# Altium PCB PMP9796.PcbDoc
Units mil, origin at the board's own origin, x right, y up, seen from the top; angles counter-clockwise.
Board outline 2600 x 2200 mil, 2 copper layers (Top Layer, Bottom Layer), stack 40 mil thick; 34 components, 11 nets, 92 pads, 50 vias.
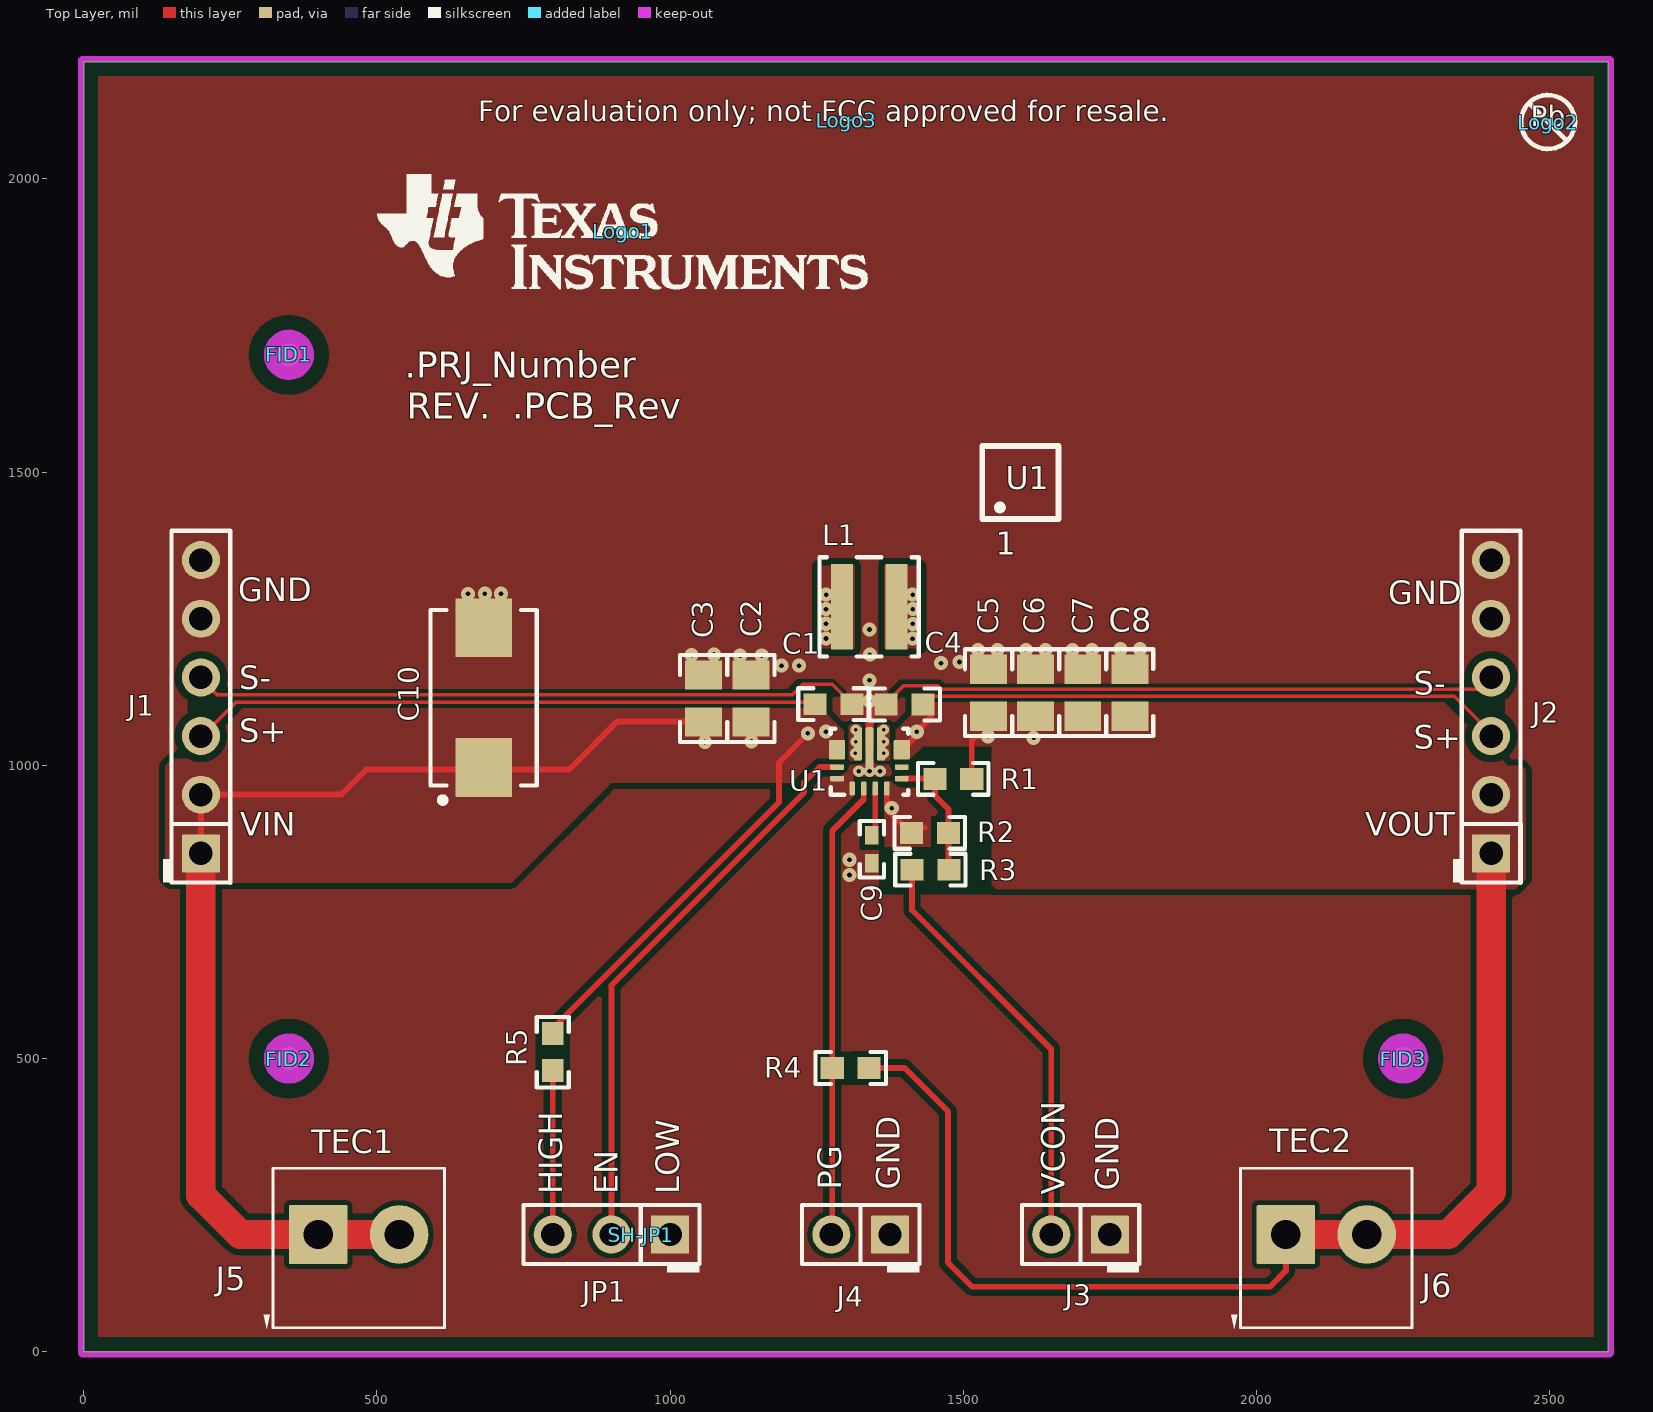
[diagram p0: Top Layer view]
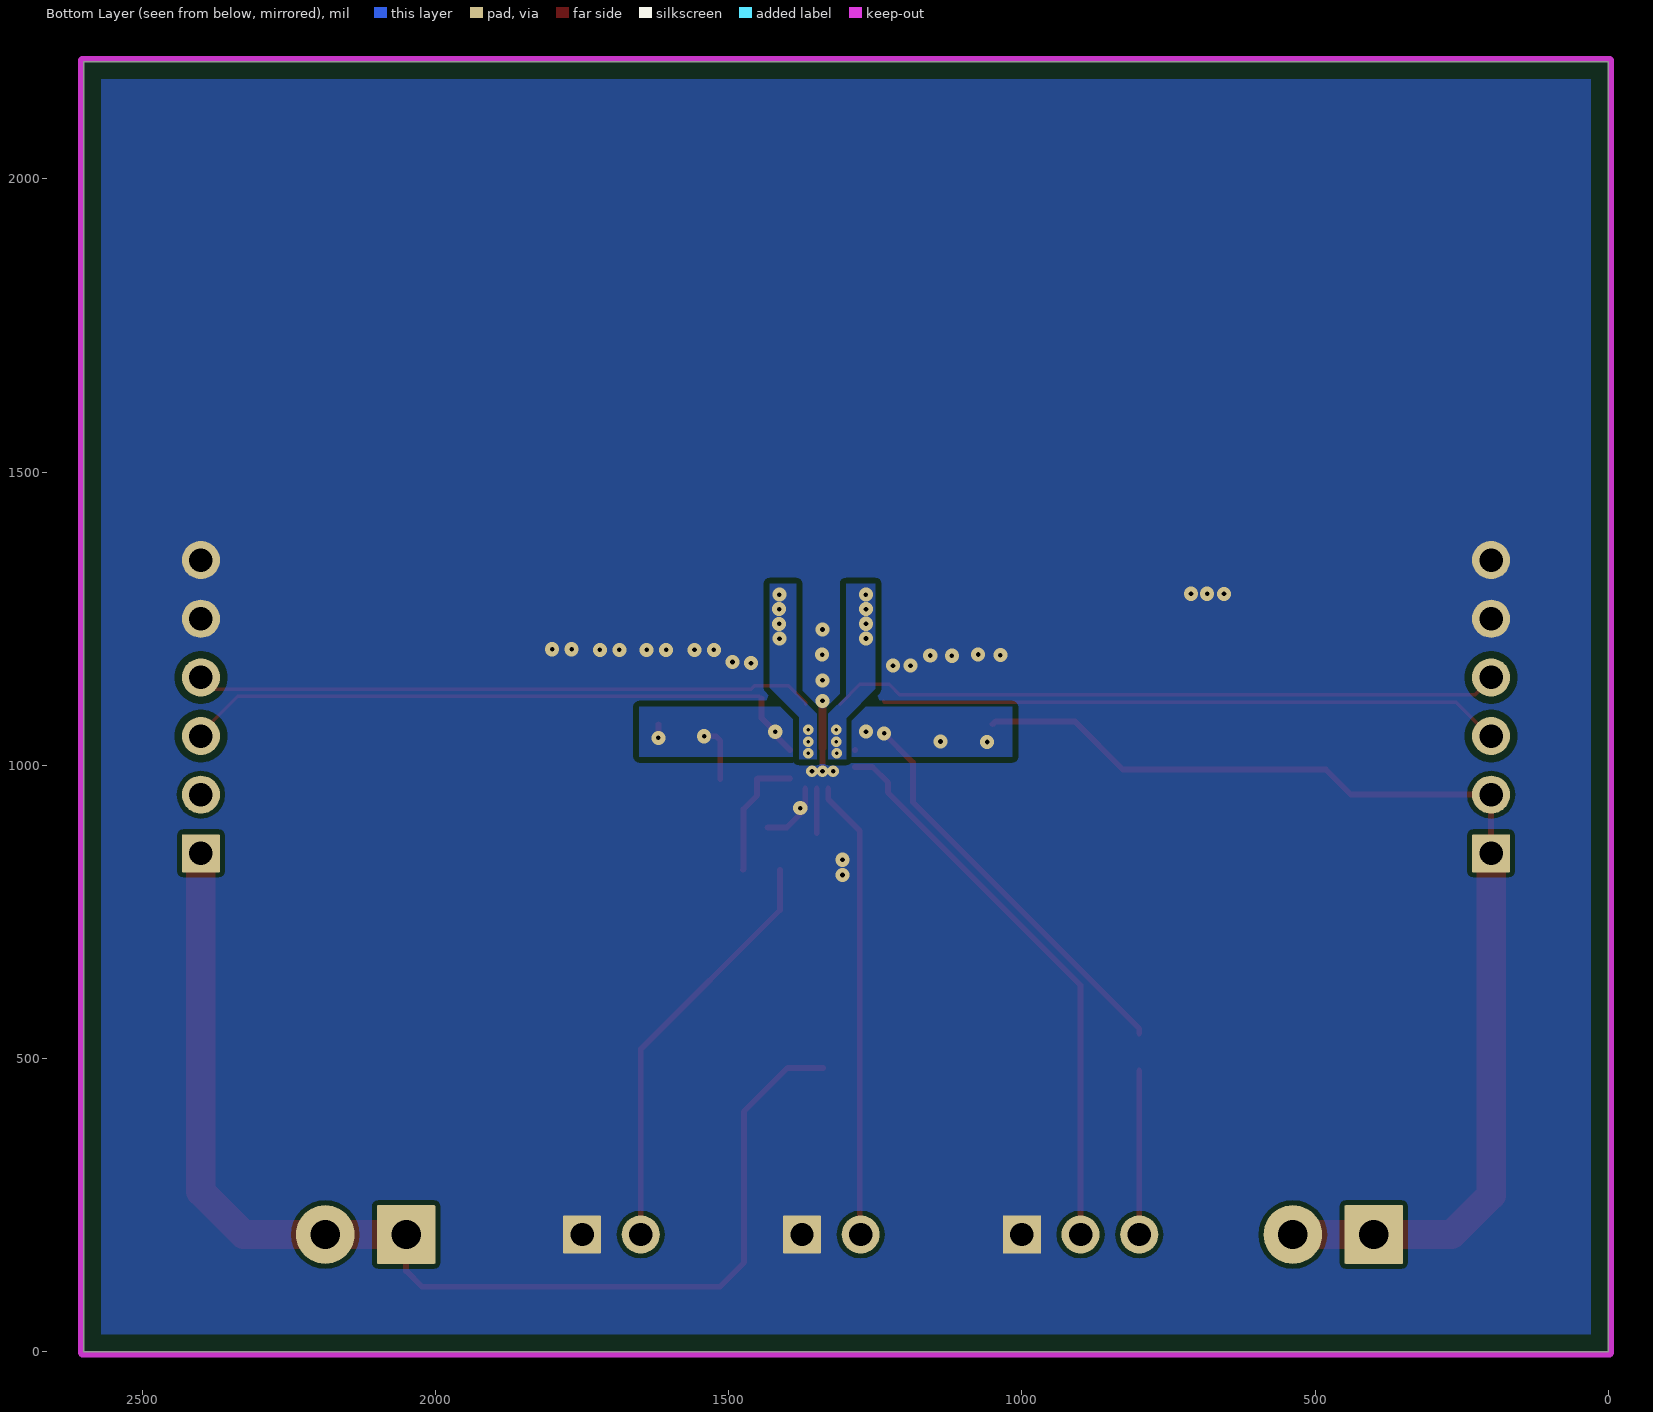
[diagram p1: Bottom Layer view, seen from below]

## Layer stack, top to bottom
Top Solder: solder mask 0.4, Solder Resist, Dk 3.5
Top Layer: signal copper 1.4
Dielectric1: core 37.2, FR-4, Dk 4.8
Bottom Layer: signal copper 1.4
Bottom Solder: solder mask 0.4, Solder Resist, Dk 3.5

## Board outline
0,0 2600,0 2600,2200 0,2200

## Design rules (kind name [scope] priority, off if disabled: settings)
AcuteAngle [All] p1: minimum=4.50000000000000E+0001 checktracksonly=FALSE
AssemblyTestPointUsage [All] p1: valid=2
Clearance Clearance_U1_Poly [InNamedPolygon('L1_L01_P015') Or InNamedPolygon('L2_L01_P016')] p1: gap=5.9
Clearance Clearance_U1 [InComponent('U1')] p2: gap=5.9
Clearance Clearance_JP4 [InComponent('JP4')] p3: gap=5.9
Clearance Clearance_Keepouts [((IsTrack Or IsArc) And Not InPoly) And IsFree and IsKeepOut vs ((IsTrack Or IsArc) And Not InPoly) And IsFree and IsKeepOut] p4: gap=0
Clearance Clearance_Pad [((ObjectKind = 'Pad') And (Layer = 'MultiLayer'))] p5: gap=8 except(6: Track-Track)
Clearance Clearance_BoardEdge_MountingHoles [OnCopper and InComponentClass('Mounting Holes') vs IsKeepOut] p6: gap=40
Clearance Clearance_BoardEdge_Poly [OnCopper and InPoly vs IsKeepOut] p7: gap=25
Clearance Clearance_BoardEdge [OnCopper and Not InComponentClass('Logo') and not InComponentClass('FiducialMark') and not InRegion(1000,500,4000,800) and Not IsKeepout vs IsKeepOut] p8: gap=36
Clearance Clearance_Poly [InPolygon] p9: gap=10
Clearance [All] p10: gap=7.87 except(6: Track-Track)
ComponentClearance ComponentClearance_1 [(InComponent('J1') OR InComponent('J2') OR InComponent('J3') OR InComponent('J4') OR InComponent('J5') OR InComponent('J6') OR InComponent('J8')OR InComponent('JP1') OR InComponent('JP2') OR InComponent('JP3') OR InComponent('JP4') OR InComponent('L1') OR InComponent('U1'))] p1: gap=0 collisioncheckmode=3 verticalgap=0 showdistances=FALSE
ComponentClearance ComponentClearance_Logo [InComponentClass('Logo')] p2: gap=50 collisioncheckmode=3 verticalgap=10 showdistances=FALSE
ComponentClearance ComponentClearance_ScrewToNut [(HasFootprint('NY PMS 440 0025 PH')) vs (HasFootprint('Keystone_1902C'))] p3: gap=5 collisioncheckmode=3 verticalgap=10 showdistances=FALSE
ComponentClearance ComponentClearance_MountingHoles [InComponentClass('Mounting Holes')] p4: gap=50 collisioncheckmode=3 verticalgap=0 showdistances=FALSE
ComponentClearance ComponentClearance_SmallPassives [HasFootprint('0201*') or HasFootprint('0402*') or HasFootprint('0508') or HasFootprint('0603*') or HasFootprint('0612') or HasFootprint('0805*') or HasFootprint('0815*') or HasFootprint('0830*') or HasFootprint('1206*') or HasFootprint('1210*') or HasFootprint('1808*') or HasFootprint('1812*') or HasFootprint('1825*') or HasFootprint('2010*') or HasFootprint('2220*') or HasFootprint('2225*') or HasFootprint('2512*') or HasFootprint('2728*') or HasFootprint('3518*') vs HasFootprint('0201*') or HasFootprint('0402*') or HasFootprint('0508') or HasFootprint('0603*') or HasFootprint('0612') or HasFootprint('0805*') or HasFootprint('0815*') or HasFootprint('0830*') or HasFootprint('1206*') or HasFootprint('1210*') or HasFootprint('1808*') or HasFootprint('1812*') or HasFootprint('1825*') or HasFootprint('2010*') or HasFootprint('2220*') or HasFootprint('2225*') or HasFootprint('2512*') or HasFootprint('2728*') or HasFootprint('3518*')] p5: gap=20 collisioncheckmode=3 verticalgap=10 showdistances=FALSE
ComponentClearance ComponentClearance_THtoSMT [IsThruComponent vs IsSMTComponent] p6: gap=30 collisioncheckmode=3 verticalgap=0 showdistances=FALSE
ComponentClearance ComponentClearance_THtoTH [IsThruComponent vs IsThruComponent] p7: gap=15 collisioncheckmode=3 verticalgap=0 showdistances=FALSE
ComponentClearance [All] p8: gap=20 collisioncheckmode=3 verticalgap=10 showdistances=FALSE
DiffPairsRouting [All] p1: maxlimit=100 minlimit=10 mostfreqgap=10 toplayer_minwidth=15 toplayer_maxwidth=15 toplayer_prefwidth=15 bottomlayer_minwidth=15 bottomlayer_maxwidth=15 bottomlayer_prefwidth=15 maxuncoupledlength=1000
FabricationTestPointUsage TestPointUsage [All] p1: valid=2 allowmultiple=FALSE
FabricationTestpoint Testpoint [All] p1: side=3 testpointundercomponent=TRUE minsize=40 maxsize=100 preferedsize=60 minholesize=0 maxholesize=40 preferedholesize=32 testpointgrid=1 allowsidetop=TRUE allowsidebottom=TRUE usegrid=TRUE gridtolerance=0.01
FanoutControl Fanout_LCC [IsLCC] p1: bgadir=Out bgaviamode=Centered fanoutstyle=Auto fanoutdirection=Alternating viagrid=1 // Fanout_LCC (Default Rule)
FanoutControl Fanout_BGA [IsBGA] p2: bgadir=Out bgaviamode=Centered fanoutstyle=Auto fanoutdirection=Alternating viagrid=1 // Fanout_BGA (Default Rule)
FanoutControl Fanout_Default [All] p4: bgadir=Out bgaviamode=Centered fanoutstyle=Auto fanoutdirection=Alternating viagrid=1 // Fanout_Default (Default Rule)
FanoutControl Fanout_Small [(CompPinCount < 5)] p5: bgadir=Out bgaviamode=Centered fanoutstyle=Auto fanoutdirection=OutThenIn viagrid=1 // Fanout_Small (Default Rule)
HoleSize HoleSize_BGA_Room [WithinRoom('BGA_Room')] p1: absolutevalues=TRUE maxlimit=100 minlimit=3.94 maxpercent=80.000 minpercent=20.000
HoleSize [All] p2: absolutevalues=TRUE maxlimit=251 minlimit=6 maxpercent=80.000 minpercent=20.000
HoleToHoleClearance HoleToHoleClearance_BGA_Room [All] p1: gap=8 allowstackedmicrovias=TRUE
HoleToHoleClearance [All] p2: gap=10 allowstackedmicrovias=TRUE
MinimumAnnularRing MinimumAnnularRing_BGA_Room [WithinRoom('BGA_Room')] p1: minimumring=3.64
MinimumAnnularRing [All] p2: minimumring=6
MinimumSolderMaskSliver MinimumSolderMaskSliver_Logo [InComponentClass('Logo') vs InComponentClass('Logo')] p1: minsoldermaskwidth=0.7
MinimumSolderMaskSliver [All] p2: minsoldermaskwidth=4
PlaneConnect [All] p1: planeconnectstyle=Relief reliefexpansion=10 reliefentries=4 reliefconductorwidth=10 reliefairgap=10
PolygonConnect PolygonConnect_Jumpers [(ObjectKind = 'Pad') And (Layer = 'MultiLayer') And (HoleDiameter = AsMM(1.016))] p1: connectstyle=Relief reliefconductorwidth=25 reliefentries=4 polygonreliefangle="90 Angle" airgapwidth=10
PolygonConnect [All] p2: connectstyle=Direct reliefconductorwidth=10 reliefentries=4 polygonreliefangle="90 Angle" airgapwidth=10
RoutingVias RoutingVias_BGA_Room [WithinRoom('BGA_Room')] p1: holewidth=28 width=50 viastyle="Through Hole" minholewidth=3.94 minwidth=11.81 maxholewidth=28 maxwidth=50
RoutingVias [All] p2: holewidth=16 width=34 viastyle="Through Hole" minholewidth=6 minwidth=18 maxholewidth=40 maxwidth=65
SMDToCorner [All] p1: distance=31496
SilkToSilkClearance SilkToSilkClearance__Pb-FreeLogo [(HasFootprint('Pb-Free_Overlay_Medium') OR HasFootprint('Pb-Free_Overlay_Small')) vs (HasFootprint('Pb-Free_Overlay_Medium') OR HasFootprint('Pb-Free_Overlay_Small'))] p1: silktosilkclearance=0
SilkToSilkClearance [All] p2: silktosilkclearance=3
SilkToSolderMaskClearance SilkscreenOverComponentPads [All] p1: minsilkscreentomaskgap=3 clearancetoexposedcopper=FALSE
SolderMaskExpansion [All] p1: expansion=2
Width [All] p1: maxlimit=100 minlimit=6 preferedwidth=10 checkconnectedcopper=TRUE
15 further rules are at their usual default settings.

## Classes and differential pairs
component class PMP9796_A: C1 C2 C3 C4 C5 C6 C7 C8 C9 C10 J1 J2 J3 J4 J5 J6 JP1 L1 R1 R2 R3 R4 R5 U1
component class AssemblyNote: ZZ2 ZZ3 ZZ4
component class FiducialMark: FID1 FID2 FID3
component class Logo: Logo1
component class Header: J1 J2 J3 J4 JP1
component class PMP9796_A_Hardware: FID1 FID2 FID3 Logo1 Logo2 Logo3 SH-JP1 ZZ2 ZZ3 ZZ4
component class Shunt: SH-JP1

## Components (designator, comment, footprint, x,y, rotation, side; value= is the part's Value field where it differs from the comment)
C1 "GRM188R61E106MA73D" 0603 1278.58,1104.22 r0 top
C2 "GRM21BC71E106ME11L" 0805_HV 1138.04,1114.05 r90 top
C3 "GRM21BC71E106ME11L" 0805_HV 1057.26,1114.05 r90 top
C4 "GRM188R61E106MA73D" 0603 1400.02,1103.88 r180 top
C5 "GRM21BC81C226ME44L" 0805_HV 1543.21,1123.91 r90 top
C6 "GRM21BC81C226ME44L" 0805_HV 1623.44,1123.91 r90 top
C7 "GRM21BC81C226ME44L" 0805_HV 1703.67,1123.91 r90 top
C8 "GRM21BC81C226ME44L" 0805_HV 1784,1124 r90 top
C9 "GRM155R71E104KE14D" 0402 1344,857 r270 top
C10 "T495D686K020ATE150" 7343-31 682.1,1115.55 r90 top
FID1 "Fiducial" Fiducial10-20 350,1700 r0 top
FID2 "Fiducial" Fiducial10-20 350,500 r0 top
FID3 "Fiducial" Fiducial10-20 2250,500 r0 top
J1 "TSW-106-07-G-S" TSW-106-07-G-S 200,1100 r90 top
J2 "TSW-106-07-G-S" TSW-106-07-G-S 2400,1100 r90 top
J3 "TSW-102-07-G-S" TSW-102-07-G-S 1700,200 r180 top
J4 "TSW-102-07-G-S" TSW-102-07-G-S 1325,200 r180 top
J5 "ED555/2DS" TERM_BLK_ED555-2DS 400,200 r0 top
J6 "ED555/2DS" TERM_BLK_ED555-2DS 2050,200 r0 top
JP1 "TSW-103-07-G-S" TSW-103-07-G-S 900,200 r180 top
L1 "XAL4020-222MEB" XAL4020 1339.61,1270.32 r0 top
Logo1 "Texas Instruments" TI_Stacked_Overlay_Small 919,1910 r0 top
Logo2 "Pb-Free Symbol" Pb-Free_Overlay_Small 2497,2097 r0 top
Logo3 "FCC disclaimer" FCC_disclaimer 1300,2100 r0 top
R1 "RC0603FR-07680KL" 0603 1483,977 r0 top
R2 "RC0603FR-07130KL" 0603 1443,885 r0 top
R3 "RC0603FR-07162KL" 0603 1444,822 r0 top
R4 "RC0603FR-07100KL" 0603 1308,484 r180 top
R5 "CRCW060310K0FKEA" 0603 800,511 r90 top
SH-JP1 "969102-0000-DA" SNT-100-BK-G 950,200 r180 top
U1 "TPS63070RNM" RNM0015A 1340,1006 r90 top
ZZ2 "These assemblies are ESD sensitive, ESD precautions shall be observed." AssemblyNote 123,2576.11 r0 top
ZZ3 "These assemblies must be clean and free from flux and all contaminants. Use of no clean flux is not acceptable." AssemblyNote 123,2487.56 r0 top
ZZ4 "These assemblies must comply with workmanship standards IPC-A-610 Class 2, unless otherwise specified." AssemblyNote 124,2399 r0 top

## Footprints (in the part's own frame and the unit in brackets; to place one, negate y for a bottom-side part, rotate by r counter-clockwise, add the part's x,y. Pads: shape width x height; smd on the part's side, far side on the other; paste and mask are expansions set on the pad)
0402 [mm] "0402 from SM-752 data"
  rect 0.8x0.6 smd: 1(-0.6,0) 2(0.6,0)
  silkscreen extent -1.22,-0.52 1.22,0.52, body extent -0.55,-0.3 0.55,0.3, height 0.6
0603 [mm] "0603 from SM-752 data"
  rect 1x0.95 smd: 1(-0.8,0) 2(0.8,0)
  silkscreen extent -1.52,-0.69 1.52,0.69, body extent -0.87,-0.47 0.87,0.47, height 1
0805_HV [mil] "0805 with 30mil clearance between pads"
  rect 50x63 smd: 1(-40,0) 2(40,0)
  silkscreen extent -74,-40 74,40, body extent -43,-29 43,29, height 57
7343-31 [mm] "Medium Density based on Kemet T495 dimensions"
  rect 2.55x2.45 smd: 1(-3.025,0) 2(3.025,0)
  silkscreen extent -4.56,-2.3 3.8,2.3, body extent -3.8,-2.3 3.8,2.3, height 3.1
AssemblyNote [mil] "Assembly Note"
FCC_disclaimer [mil]
Fiducial10-20 [mm]
  round 1 smd mask+0.5: 1(0,0)
  Top Layer keep-out circle w1.178: c0,0 r0.5
Pb-Free_Overlay_Small [mil]
  silkscreen extent -46,-46 46,46
RNM0015A [mm] "PVQFN, 13-Leads, Body 3x2.5mm"
  rrect40% 0.25x0.6 on Top Paste: 0(0.275,1.4) 0(0.275,-1.4) 0(0.775,1.4) 0(0.775,-1.4)
  rrect40% 0.25x0.6 on Top Solder: 0(0.275,1.4) 0(0.275,-1.4) 0(0.775,1.4) 0(0.775,-1.4)
  rrect40% 0.75x0.25 on Top Paste: 0(0.525,1.225) 0(0.525,-1.225)
  rrect40% 0.75x0.25 on Top Solder: 0(0.525,1.225) 0(0.525,-1.225)
  rrect40% 0.72x0.25 on Top Paste: 0(1.06,0) 1(0.14,0)
  rrect42% 0.6x0.24 smd: 1(-1.15,0.75) 2(-1.15,0.25) 3(-1.15,-0.25) 4(-1.15,-0.75)
  rrect40% 0.575x0.25 on Top Paste: 1(0.388,0.5) 1(0.388,-0.5) 1(1.163,-0.5) 1(1.163,0.5)
  rrect42% 0.24x0.6 smd: 5(-0.725,-1.4) 6(-0.225,-1.4) 14(-0.225,1.4) 15(-0.725,1.4)
  rrect17% 0.85x0.7 smd paste-0.35 mask-0.35: 7(0.525,-1.4) 8(0.525,-1.4) 12(0.525,1.4) 13(0.525,1.4)
  rrect42% 1.45x0.35 smd paste-0.18 mask-0.05: 9(0.775,-0.5) 11(0.775,0.5)
  rrect42% 1.8x0.35 smd paste-0.18 mask-0.05: 10(0.6,0)
  silkscreen extent -1.43,-1.68 1.43,1.68, body extent -1.33,-1.58 1.33,1.58, height 1.01
SNT-100-BK-G [mil] "Samtec STEP model"
  round 1 on Mech3: 0(0,0)
  body extent -100,-50 100,50, height 344
TERM_BLK_ED555-2DS [mil]
  rrect4% 100x100 hole 50: 1(0,0)
  round 100 hole 50: 2(138,0)
  silkscreen extent -93,-161 215,113, body extent -69,-150 207,106, height 323
TI_Stacked_Overlay_Small [mil]
  silkscreen extent -418,-98 418,98
TSW-102-07-G-S [mm] "Samtec 100mil, 1x2, 230 mil above insulator"
  rrect6% 1.65x1.65 hole 1.016: 1(-1.27,0)
  round 1.65 hole 1.016: 2(1.27,0)
  silkscreen extent -2.54,-1.27 2.54,1.65, body extent -2.54,-1.27 2.54,1.27, height 8.38
TSW-103-07-G-S [mm] "Samtec 100mil, 1x3, 230 mil above insulator"
  rect 1.65x1.65 hole 1.016: 1(-2.54,0)
  round 1.65 hole 1.016: 2(0,0) 3(2.54,0)
  silkscreen extent -3.81,-1.27 3.81,1.65, body extent -3.81,-1.27 3.81,1.27, height 8.38
TSW-106-07-G-S [mm] "Samtec 100mil, 1x6, 230 mil above insulator"
  rrect6% 1.65x1.65 hole 1.016: 1(-6.35,0)
  round 1.65 hole 1.016: 2(-3.81,0) 3(-1.27,0) 4(1.27,0) 5(3.81,0) 6(6.35,0)
  silkscreen extent -7.62,-1.27 7.62,1.65, body extent -7.62,-1.27 7.62,1.27, height 8.38
XAL4020 [mil] "Coilcraft XAL4020 7/18/12"
  rect 38x146 smd: 1(-46.5,0) 2(46.5,0)
  silkscreen extent -84,-84 85,84, body extent -84,-84 84,84, height 83

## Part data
C1 C4: "CAP, CERM, 10 µF, 25 V, +/- 20%, X5R, 0603"
C2 C3: "CAP, CERM, 10 µF, 25 V, +/- 20%, X7S, 0805"
C5 C6 C7 C8: "CAP, CERM, 22 µF, 16 V, +/- 20%, X6S, 0805"
C9: "CAP, CERM, 0.1 µF, 25 V, +/- 10%, X7R, 0402"
C10: "CAP, TA, 68 µF, 20 V, +/- 10%, 0.15 ohm, SMD"
FID1 FID2 FID3: "Fiducial mark.  There is nothing to buy or mount."
J1 J2: "Header, 100mil, 6x1, Gold, TH"
J3 J4: "Header, 100mil, 2x1, Gold, TH"
J5 J6: "Terminal Block, 3.5mm Pitch, 2x1, TH"
JP1: "Header, 100mil, 3x1, Gold, TH"
L1: "Inductor, Shielded, Composite, 2.2 µH, 5.5 A, 0.04 ohm, SMD"
Logo1: library part TI_Logo, "Texas Instrument Corporate Signature"
Logo2: library part Pb-Free
Logo3: library part FCC_disclaimer, "FCC_disclaimer"
R1: "RES, 680 k, 1%, 0.1 W, 0603"
R2: "RES, 130 k, 1%, 0.1 W, 0603"
R3: "RES, 162 k, 1%, 0.1 W, 0603"
R4: "RES, 100 k, 1%, 0.1 W, 0603"
R5: "RES, 10.0 k, 1%, 0.1 W, 0603"
SH-JP1: "Shunt, 100mil, Gold plated, Black"
U1: "TPS63070RNM, RNM0015A"
ZZ2 ZZ3 ZZ4: library part AssemblyNote

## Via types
v1: diameter 24, hole 8, Top Layer to Bottom Layer, tented both sides, 41 vias
v2: diameter 18, hole 6, Top Layer to Bottom Layer, tented both sides, 6 vias
v3: diameter 20, hole 8, Top Layer to Bottom Layer, tented both sides, 3 vias

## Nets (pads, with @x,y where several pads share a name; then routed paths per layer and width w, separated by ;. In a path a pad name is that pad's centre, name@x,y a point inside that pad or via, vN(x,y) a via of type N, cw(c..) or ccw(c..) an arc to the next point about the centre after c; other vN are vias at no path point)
EN: JP1.2 U1.14 | length 974.2
  Top Layer w10: JP1.2 900,624.95 1228.55,953.49 1228.55,970.99 1254.7,997.14 U1.14
FB: R1.1 R2.2 R3.2 U1.5 | length 221.5
  Top Layer w10: U1.5 1451.05,977.46 R1.1 1451.5,948.5 1474.5,925.5 R2.2 1474.5,823 R3.2
GND: C1.2 C2.2 C3.2 C4.2 C5.2 C6.2 C7.2 C8.2 C9.2 C10.2 J1.4 J1.5 J1.6 J2.4 J2.5 J2.6 J3.1 J4.1 JP1.1 R2.1 U1.1@1310.47,960.72 U1.4 U1.10 U1.15 | length 2468.6
  Top Layer w6: J1.4@199,1149 227.93,1120.07 1208.07,1120.07 1226,1138 1276.29,1138 C1.2 ; C4.2 1368.52,1106.52 1398,1136 1456,1136 1462,1130 2386,1130 J2.4@2401,1145
  Top Layer w10: v3(1322,990) v3(1340,990) ; U1.10 v3(1340,990) ; v3(1358,990) v3(1340,990) ; v1@1369.53,925.47 U1.4 ; v1@1370,925 1401,894 1416,894 1434,894
  Top Layer w13.7: U1.10 v1(1340,1110)
  other v1: 1306,813 1306,839 1378,927 1340.23,1145 1190,1170 1220,1170 1461.99,1174.22 1493.46,1176.13 1119.51,1186.84 1156.29,1187.35 1036.75,1187.86 1074.55,1188.89 1340.76,1188.68 1525.28,1197 1558.49,1197 1606.62,1197 1639.83,1197 1686.59,1197 1719.79,1197 1767.79,1198 1801,1198 1340.23,1231.52 655.28,1292.45 684.14,1292.58 711.63,1292.58
HIGH: JP1.3 R5.1 | length 279.5
  Top Layer w10: JP1.3 R5.1
L1: L1.1 U1.11
  other v1: 1265.75,1216.4 1265.95,1241.42 1266.05,1266.33 1266.15,1291.14
  other v2: 1315.89,1020.68 1316.26,1040.56 1316.26,1060.49
L2: L1.2 U1.9
  other v1: 1413.25,1216.13 1413.89,1241.33 1413.89,1266.32 1413.68,1291.09
  other v2: 1364.25,1020.85 1364.17,1040.46 1364.25,1060.6
NetJ3_2: J3.2 R3.1 | length 720.4
  Top Layer w10: R3.1 1412.5,753.5 1650,516 J3.2
PG: J4.2 R4.2 U1.2 | length 783.6
  Top Layer w10: J4.2 1276.5,201.5 R4.2 1276.5,888.5 1330.16,942.16 U1.2
VAUX: C9.1 U1.3 | length 76.4
  Top Layer w10: C9.1@1349.84,884.3 U1.3
VIN: C1.1 C2.1 C3.1 C10.1 J1.1 J1.2 J1.3 J5.1 J5.2 R5.2 U1.12 U1.13 | length 3721.6
  Top Layer w6: J1.3@200.82,1049.18 201.18,1049.18 259.99,1107.99 1234.65,1107.99 C1.1@1235.67,1109
  Top Layer w10: J1.1 J1.2 438.81,950 481.46,992.65 827.63,992.65 910,1075.02 1044.98,1075.02 C3.1@1050,1070 ; J1.3@200.82,1049.18 J1.3 J1.3@210.05,1060.05 ; R5.2 800,551.4 1186,937.4 1186,1005 v1@1236,1055 ; U1.12@1284.25,1026.32 U1.12@1284.88,1025.68
  Top Layer w50: J1.1 200,267 267,200 J5.1 J5.2
  other v1: 1059.23,1039.71 1138.92,1040.74 1235.04,1054.66 1266.04,1057.54
VOUT: C4.1 C5.1 C6.1 C7.1 C8.1 J2.1 J2.2 J2.3 J6.1 J6.2 R1.2 R4.1 U1.7 U1.8 | length 3287.6
  Top Layer w6: C4.1@1444.38,1114.38 1448,1118 2337,1118 2400,1055 J2.3
  Top Layer w10: R4.1 1400,484 1474,410 1474,152 1515,111 2023,111 2050,138 J6.1 ; U1.7@1395.12,1025.68 1420.63,1051.19 v1(1420.63,1057.26) 1444.38,1080.99 C4.1@1444.38,1114.38 ; R1.2 1514.5,1042.5 1521.69,1049.69 v1(1541.88,1049.69) ; v1(1620,1046.94) C6.1@1620,1070 ; J2.3@2381.84,1066.84 J2.3
  Top Layer w50: J6.1 J6.2 2327,200 2400,273 J2.1
pads on no net: FID1.1 FID2.1 FID3.1 SH-JP1.0 U1.0 U1.1@1320.32,1021.28 U1.1@1320.32,1051.79 U1.1@1340,1011.51 U1.1@1359.68,1021.28 U1.1@1359.68,1051.79 U1.6

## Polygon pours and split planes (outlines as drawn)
VIN on Top Layer "VIN_L01_P020" (solid, remove dead copper, pour order 20): 1258,1097 1296.37,1058.63 1296.37,1010.95 1248.7,1010.95 1207.75,970 900,970 890,960 730,800 147,800 139,808 139,999 150.95,1010.95 185.07,1010.95 271.11,1097 835.19,1097
VOUT on Top Layer "VOUT_L01_P021" (solid, remove dead copper, pour order 21): 2459,992.21 2451.64,999.57 2428.42,999.57 2319.99,1108 1433,1108 1385,1060 1385,1011.73 1410.2,1011.73 1431.39,1032.92 1548.64,1032.92 1548.64,982.48 1548.64,914.55 1548.64,796.36 1556.48,788.52 1914.97,788.52 2441.52,788.52 2459,806
L1 on Top Layer "L1_L01_P022" (solid, remove dead copper, pour order 22): 1315,1200 1252.69,1200 1252.69,1340 1315,1340
L2 on Top Layer "L2_L01_P024" (solid, remove dead copper, pour order 24): 1365,1200 1365,1340 1426.29,1340 1426.29,1200
L1 on Top Layer "L1_L01_P015" (solid, remove dead copper, pour order 15): 1307.84,1070.15 1324.15,1070.15 1327.03,1067.27 1327.03,1009.97 1325.01,1007.95 1307.34,1007.95 1304.8,1010.5 1304.8,1067.12
L2 on Top Layer "L2_L01_P016" (solid, remove dead copper, pour order 16): 1356.81,1070.29 1370.95,1070.29 1374.9,1066.34 1375.22,1009.9 1373.29,1007.97 1354.95,1007.97 1353,1009.92 1353,1066.48
GND on Top Layer "GND_L01_P026" (solid, remove dead copper, pour order 26): -8.22,2204.01 2595.99,2204.01 2600,2200 2600,0 0,0 0,2200
VIN on Bottom Layer "VIN_L02_P012" (solid, remove dead copper, pour order 12): 1292.56,1099.54 1016.66,1099.54 1016.66,1014.48 1292.56,1014.48
GND on Bottom Layer "GND_L02_P014" (solid, remove dead copper, pour order 14): 30,2170 2570,2170 2570,30 30,30
VOUT on Bottom Layer "VOUT_L02_P013" (solid, pour order 13): 1652.46,1015.05 1652.46,1099.92 1390.73,1099.92 1390.73,1015.05
L1 on Bottom Layer "L1_L02_P011" (solid, remove dead copper, pour order 11): 1250,1310 1300,1310 1300,1117.79 1330,1087.79 1330,1010.35 1300,1010.35 1300,1080.5 1250,1130.5
L2 on Bottom Layer "L2_L02_P010" (solid, remove dead copper, pour order 10): 1350,1010.36 1380,1010.36 1380,1082.33 1430,1132.33 1430,1145 1430,1310 1385,1310 1385,1123.16 1350,1088.16

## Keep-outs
Keep-Out Layer:
  lines w10: -5,0 ccw(c0,0) 0,-5 ; -5,0 ccw(c0,0) 0,-5 ; -5,0 -5,2200 ; -5,2200 cw(c0,2200) 0,2205 ; -5,2200 cw(c0,2200) 0,2205 ; 0,-5 2600,-5 ; 0,2205 2600,2205 ; 2600,-5 ccw(c2600,0) 2605,0 ; 2600,-5 ccw(c2600,0) 2605,0 ; 2600,2205 cw(c2600,2200) 2605,2200 ; 2600,2205 cw(c2600,2200) 2605,2200 ; 2605,0 2605,2200
  text ".Layer_Name" at 577,-858.49 h60

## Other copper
Top Layer:
  pour cut-out: 1355.79,861 1355.79,779 1547,779 1547,861
  pour cut-out: 1313,980.37 1378.1,980.37 1378.1,972.67 1313,972.67
  pour cut-out: 1200,1130 1217,1147 1279,1147 1300,1126 1300,1118 1283,1118 1272,1129 1230,1129 1213,1112 248.58,1112 223.83,1087.26 177.26,1087.26 177.26,1118 177.26,1130
  pour cut-out: 1372,1126 1392,1146 1461,1146 1468,1139 2423.24,1139 2423.24,1045.97 2423.24,1087.14 2382.08,1087.14 2347.21,1122 1398,1122 1388,1112 1372,1112
  pour cut-out: 2355.33,1050 ccw(c2400,1050) 2400,1005.33 ccw(c2400,1050) 2444.67,1050 ccw(c2400,1050) 2400,1094.67 ccw(c2400,1050)
  pour cut-out: 155.33,1150 ccw(c200,1150) 200,1105.33 ccw(c200,1150) 244.67,1150 ccw(c200,1150) 200,1194.67 ccw(c200,1150)
  pour cut-out: 155.33,1050 ccw(c200,1050) 200,1005.33 ccw(c200,1050) 244.67,1050 ccw(c200,1050) 200,1094.67 ccw(c200,1050)
  pour cut-out: 2355.33,1150 ccw(c2400,1150) 2400,1105.33 ccw(c2400,1150) 2444.67,1150 ccw(c2400,1150) 2400,1194.67 ccw(c2400,1150)
  text ".Layer_Name" at 577,-858.49 h60
Bottom Layer:
  pour cut-out: 2355.33,1150 ccw(c2400,1150) 2400,1105.33 ccw(c2400,1150) 2444.67,1150 ccw(c2400,1150) 2400,1194.67 ccw(c2400,1150)
  pour cut-out: 2355.33,1050 ccw(c2400,1050) 2400,1005.33 ccw(c2400,1050) 2444.67,1050 ccw(c2400,1050) 2400,1094.67 ccw(c2400,1050)
  pour cut-out: 155.33,1150 ccw(c200,1150) 200,1105.33 ccw(c200,1150) 244.67,1150 ccw(c200,1150) 200,1194.67 ccw(c200,1150)
  pour cut-out: 155.33,1050 ccw(c200,1050) 200,1005.33 ccw(c200,1050) 244.67,1050 ccw(c200,1050) 200,1094.67 ccw(c200,1050)
  text ".Layer_Name" at 577,-858.49 h60

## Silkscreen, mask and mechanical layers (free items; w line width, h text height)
Top Overlay:
  circle w10: c1562.36,1439.78 r5.1
  lines w10: 1532.36,1420.38 1532.36,1544.38 1662.36,1544.38 1662.36,1420.38 1532.36,1420.38
  text ".PRJ_Number" at 548,1661 h45
  text "REV." at 551.4,1591.09 h45
  text ".PCB_Rev" at 731,1591 h45
  text "U1" at 1572.36,1471.04 h39.37
  text "1" at 1555.09,1358.88 h39.37
  text "GND" at 263.93,1279.87 h40
  text "GND" at 2225,1275 h40
  text "S-" at 265.5,1130.09 h40
  text "S-" at 2268.29,1120.25 h40
  text "S+" at 265.5,1039.02 h40
  text "S+" at 2268.29,1028.35 h40
  text "VIN" at 267.2,880 h40
  text "VOUT" at 2185,880 h40
  text "TEC2" at 2021.56,340.38 h40
  text "TEC1" at 388.56,338.38 h40
  text "PG" at 1291.62,276.56 h40 r90
  text "GND" at 1391.27,276.56 h40 r90
  text "GND" at 1765.27,274.56 h40 r90
  text "HIGH" at 815.89,269 h40 r90
  text "EN" at 910.89,269 h40 r90
  text "LOW" at 1015.89,269 h40 r90
  text "VCON" at 1672.62,267.56 h40 r90
  text ".Layer_Name" at 577,-858.49 h60
Bottom Overlay:
  text ".Layer_Name" at 577,-858.49 h60
Top Paste:
  text ".Layer_Name" at 577,-858.49 h60
Bottom Paste:
  text ".Layer_Name" at 577,-858.49 h60
Top Solder:
  text ".Layer_Name" at 577,-858.49 h60
  text ".Layer_Name" at 577,-858.49 h60
Bottom Solder:
  text ".Layer_Name" at 577,-858.49 h60
Drill Guide:
  text ".Layer_Name" at 577,-858.49 h60
M1 Board Outline:
  the board outline again, w10
  text ".Layer_Name" at 577,-858.49 h60
M2 Board Dimensions:
  rectangle: 124.5,-410.5 499.5,-285.5
  rectangle: -0.5,-285.5 124.5,-160.5
  lines w7: -0.5,-285.5 999.5,-285.5 ; 124.5,-410.5 124.5,-160.5 ; 249.5,-410.5 249.5,-160.5 ; 499.5,-410.5 499.5,-160.5 ; 749.5,-410.5 749.5,-160.5 ; -0.5,-410.5 -0.5,-160.5 999.5,-160.5 999.5,-410.5 -0.5,-410.5
  lines w10: -0.5,-475.5 -0.5,-455.5 ; 59.5,-485.5 -0.5,-465.5 ; 59.5,-445.5 -0.5,-465.5 ; 223.58,-465.5 -0.5,-465.5 ; 775.42,-465.5 999.5,-465.5 ; 939.5,-485.5 999.5,-465.5 ; 939.5,-445.5 999.5,-465.5 ; 999.5,-475.5 999.5,-455.5
  text "1000 (mil)" at 233.58,-501.49 h60
  text ".Layer_Name" at 577,-858.49 h60
M3 3D STEP Top:
  text ".Layer_Name" at 577,-858.49 h60
M4 3D STEP Bottom:
  text ".Layer_Name" at 577,-858.49 h60
M5 Assembly Top:
  lines w10: -292,-930.17 6308,-930.17 ; -292,-726.83 6310,-726.83 ; -292,-523.5 -292,-1133.5 3713,-1133.5 6310,-1133.5 6310,-523.5 -291.5,-523.5 -291.5,-1133.5 1284,-1133.5 ; 2173,-1133.5 2173,-523.5 ; 3440,-726.83 3440,-523.5 ; 4280,-726.83 4280,-523.5 ; 4902,-1140 4902,-937.17
  text "COMPONENTS MARKED 'DNP' SHOULD NOT BE POPULATED." at 1153.5,-318.5 h60
  text "ASSEMBLY VARIANT:" at 1153,-434 h60
  text ".VariantName" at 2189,-434 h60
  text "PCB VIEWED FROM TOP SIDE" at -228.5,-655.67 h60
  text "BOARD #:" at 2248,-655.67 h60
  text ".PRJ_Number" at 2793.5,-655.67 h60
  text "REV:" at 3638,-655.67 h60
  text ".PCB_Rev" at 3929.5,-655.67 h60
  text "SVN REV:" at 4476,-655.67 h60
  text ".VersionControl_RevNumber" at 4982,-655.67 h60
  text "IGNORE ->" at -228.5,-858.49 h60
  text "PLOT NAME =" at -228.5,-1064.34 h60
  text ".plot_File_Name" at 577,-1064.34 h60
  text "GENERATED    :" at 2250,-1064.34 h60
  text ".Print_Date" at 3119.5,-1064.34 h60
  text ".Print_Time" at 3848.5,-1064.34 h60
  text "TEXAS INSTRUMENTS" at 5113,-1064.34 h60
M6 Assembly Bottom:
  lines w10: -292.5,-727.33 6309.5,-727.33 ; -290.5,-930.67 6309.5,-930.67 ; 1115.5,-1140.5 1115.5,-937.67 ; 1737.5,-727.33 1737.5,-524 ; 2577.5,-727.33 2577.5,-524 ; 3844.5,-1134 3844.5,-524 ; 4733.5,-1134 6309,-1134 6309,-524 -292.5,-524 -292.5,-1134 2304.5,-1134 6309.5,-1134 6309.5,-524
  text "COMPONENTS MARKED 'DNP' SHOULD NOT BE POPULATED." at 6102,-318 h60
  text ".VariantName" at 5058,-434 h60
  text "ASSEMBLY VARIANT:" at 6097,-434 h60
  text ".VersionControl_RevNumber" at 1035.5,-656.17 h60
  text "SVN REV:" at 1541.5,-656.17 h60
  text ".PCB_Rev" at 2088,-656.17 h60
  text "REV:" at 2379.5,-656.17 h60
  text ".PRJ_Number" at 3224,-656.17 h60
  text "BOARD #:" at 3769.5,-656.17 h60
  text "PCB VIEWED FROM BOTTOM SIDE" at 6246,-656.17 h60
  text "IGNORE ->" at 2547.85,-858.49 h60
  text "TEXAS INSTRUMENTS" at 904.5,-1064.84 h60
  text ".Print_Time" at 2169,-1064.84 h60
  text ".Print_Date" at 2898,-1064.84 h60
  text "GENERATED    :" at 3767.5,-1064.84 h60
  text ".plot_File_Name" at 5440.5,-1064.84 h60
  text "PLOT NAME =" at 6246,-1064.84 h60
M9 Title Sheet:
  drawing of 57 lines, arcs and shapes, not listed
  text "1" at 739.84,8036.5 h70
  text "2" at 3235.5,8036.5 h70
  text "3" at 5724.84,8036.5 h70
  text "4" at 8231.51,8036.5 h70
  text "5" at 10730.5,8036.5 h70
  text "6" at 13235.5,8036.5 h70
  text "A" at -416.5,6893.5 h70
  text "A" at 14383.5,6893.5 h70
  text "B" at -416.5,4513.5 h70
  text "B" at 14383.5,4513.5 h70
  text "C" at -416.5,2138.5 h70
  text "C" at 14383.5,2138.5 h70
  text "PROJECT TITLE:" at 11343.5,277.5 h45
  text ".PRJ_Title" at 11393.5,144.17 h70
  text "DESIGNED FOR:" at 11343.5,-23.5 h45
  text ".PRJ_Customer" at 11393.5,-163.5 h70
  text "D" at -416.5,-231.5 h70
  text "D" at 14383.5,-231.5 h70
  text "FILE NAME:" at 11343.5,-323.5 h45
  text ".PCB_File_Name_No_Path" at 11393.5,-443.5 h70
  text "Texas Instruments (TI) and/or its licensors do not warrant the accuracy or completeness of this specification" at 6374,-605.34 h45
  text "ENGINEER:" at 11343.5,-613.5 h45
  text "LAYOUT BY:" at 12848.5,-613.5 h45
  text "or any information contained therein. TI and/or its licensors do not warrant that this design will meet" at 6329.01,-718 h45
  text ".PRJ_Engineer" at 11393.5,-768.49 h70
  text ".PCB_Layout" at 12899,-768.49 h70
  text "the specifications, will be suitable for your application or fit for any particular purpose, or will operate in" at 6329.01,-830.67 h45
  text ".Layer_Name" at 577,-858.49 h60
  text "ALTIUM DESIGNER VERSION:" at 12848.5,-923.5 h45
  text "an implementation. TI and/or its licensors do not warrant that the design is production worthy. You should" at 6329.01,-943.33 h45
  text "completely validate and test your design implementation to confirm the system functionality for your application." at 6374,-1056 h45
  text ".print_Scale" at 11393.5,-1056.83 h70
  text ".Application_BuildNumber" at 12899,-1056.83 h70
  text "1" at 739.84,-1263.5 h70
  text "2" at 3235.5,-1263.5 h70
  text "3" at 5724.84,-1263.5 h70
  text "4" at 8231.51,-1263.5 h70
  text "5" at 10730.5,-1263.5 h70
  text "6" at 13235.5,-1263.5 h70
M10 Fab Notes:
  drawing of 185 lines, arcs and shapes, not listed
  text "DESIGN INFORMATION" at 12376.42,5919.2 h60
  text "MIN. TRACK WIDTH:" at 11731.86,5739.2 h60
  text "10" at 12828.1,5739.2 h60
  text "MIL" at 12982.86,5739.2 h60
  text "5.9" at 12773.76,5609.08 h60
  text "MIN. CLEARANCE:" at 11731.86,5607.2 h60
  text "MIL" at 12982.86,5607.2 h60
  text "MIN. VIA PAD SIZE:" at 11731.86,5475.2 h60
  text "20" at 12798.11,5475.2 h60
  text "MIL" at 12982.86,5475.2 h60
  text "0.152mm (6MIL)" at 12426.86,5333.49 h60
  text "MINIMUM ANNULAR RING" at 11402.63,5329.2 h60
  text "EXTERNAL" at 13134.86,5329.2 h60
  text "PER" at 11602.63,5211.2 h60
  text "IPC-D-275 CLASS 2 LEVEL C" at 11822.63,5211.2 h60
  text "MIL, HOLES" at 13310.86,5098.91 h60
  text "+/-" at 12918.4,5098.2 h60
  text "+/-" at 13772.4,5098.2 h60
  text "REGISTRATION TOLERANCES:" at 11402.63,5093.2 h60
  text "METAL" at 12602.4,5093.2 h60
  text "5" at 13178.6,5093.2 h60
  text "3" at 14011.6,5093.2 h60
  text "MIL" at 14127.86,5093.2 h60
  text "MATERIAL:" at 11327.86,4883.74 h60
  text "FR-4 High Tg" at 12314.3,4743.41 h60
  text "FR-408" at 11748.86,4734.84 h60
  text "X" at 12160.86,4734.84 h60
  text "OTHER" at 13236.86,4734.84 h60
  text "62 MIL (1.6mm) +/-10%" at 12068.96,4572.12 h60
  text "40 MIL+/-10%" at 13650.82,4570.12 h60
  text "THICKNESS:" at 11402.63,4567.84 h60
  text "X" at 13231.44,4567.84 h60
  text "OTHER" at 13353.86,4567.84 h60
  text "TOLERANCE:" at 11402.63,4409.84 h60
  text "X" at 12241.93,4409.84 h60
  text "ANSI IPC-6012 TYPE 3 CLASS 2" at 12428.88,4409.84 h60
  text "OTHER +/-" at 12428.86,4253.84 h60
  text "BOW & TWIST:" at 11402.63,4096.84 h60
  text "X" at 12241.93,4096.84 h60
  text "ANSI IPC-6012 TYPE 3 CLASS 2" at 12428.88,4096.84 h60
  text "OTHER +/-" at 12428.86,3938.33 h60
  text "DRILLING:" at 11327.86,3799.84 h60
  text "REFERENCE:" at 11402.63,3682.84 h60
  text "X" at 12050.86,3682.84 h60
  text "AS SHOWN" at 12237.86,3682.84 h60
  text "X" at 12951.86,3682.84 h60
  text "NC_DRILL FILES" at 13088.86,3682.84 h60
  text "PTH MIN COPPER THICKNESS:" at 11402.63,3524.84 h60
  text "X" at 12752.86,3524.84 h60
  text "1MIL" at 12889.86,3524.84 h60
  text "OTHER" at 13386.86,3524.84 h60
  text "BOARD FINISH:" at 11327.86,3365.84 h60
  text "SILKSCREEN:" at 11483.08,3247.84 h60
  text "X" at 12431.86,3247.84 h60
  text "TOP" at 12557.86,3247.84 h60
  text "BOTTOM" at 13068.86,3247.84 h60
  text "SILKSCREEN COLOR:" at 11483.08,3080.84 h60
  text "X" at 12430.82,3080.84 h60
  text "WHITE" at 12557.86,3080.84 h60
  text "OTHER" at 13068.86,3080.84 h60
  text "SOLDER RESIST COLOR:" at 11483.08,2910.84 h60
  text "X" at 12050.82,2751.64 h60
  text "GREEN" at 12177.86,2751.64 h60
  text "BLUE" at 12768.86,2751.64 h60
  text "OTHER" at 13306.86,2751.64 h60
  text "IMMERSION GOLD (ENIG)" at 12388.86,2563.12 h60
  text "ENEPIG" at 13726.4,2559.84 h60
  text "SURFACE FINISH:" at 11327.86,2558.84 h60
  text "X" at 12201.91,2558.84 h60
  text "IMM. TIN/SILVER OR EQUIV" at 11657.4,2401.84 h60
  text "OTHER" at 13088.86,2401.84 h60
  text "ARRAY/PANEL:" at 11327.86,2222.84 h60
  text "CUT AND TRIM PER MECH LAYER 1" at 12388.86,2218.55 h60
  text "N.C. ROUTE" at 12388.86,2066.84 h60
  text "X" at 13067.86,2066.84 h60
  text "V. SCORE" at 13254.86,2066.84 h60
  text "CERTIFICATION:" at 11327.86,1929.84 h60
  text "MATERIALS AND WORKMANSHIP FOR ALL PCBS" at 12052.86,1929.84 h60
  text "TO MEET OR EXCEED THE REQUIREMENTS OF:" at 12052.86,1831.84 h60
  text "X" at 11679.36,1695.33 h60
  text "ANSI IPC-A-600F CLASS ->" at 11818.36,1695.33 h60
  text "X" at 13457.42,1695.33 h60
  text "2" at 13576.36,1695.34 h60
  text "1" at 13261.36,1693.84 h60
  text "3" at 13930.36,1693.84 h60
  text "X" at 11681.42,1535.84 h60
  text "UL 94V-0" at 11818.36,1535.84 h60
  text "X" at 12493.42,1535.84 h60
  text "RoHS" at 12630.36,1535.84 h60
  text "OTHER" at 13274.76,1535.84 h60
  text "PER ORDER" at 13671.82,1535.84 h60
  text "ADDITIONAL REQUIREMENTS:" at 11327.86,1394.84 h60
  text "MICROSECTION:" at 11402.63,1279.84 h60
  text "YES" at 12308.36,1279.84 h60
  text "REQUIRED" at 13169.86,1123.69 h60
  text "BARE BOARD ELEC. TEST:" at 11402.63,1120.84 h60
  text "NONE" at 12708.36,1120.84 h60
  text "X" at 13042.86,1120.84 h60
  text "PER ORDER" at 13761.86,1120.84 h60
  text "MANUFACTURER'S UL:" at 11402.63,963.84 h60
  text "RAIL" at 12568.36,959.55 h60
  text "METAL" at 13060.17,959.55 h60
  text "SILK" at 13571.86,959.55 h60
  text "X" at 13435.4,959.2 h60
  text ".Layer_Name" at 577,-858.49 h60
M11 Gerber Information:
  lines w10: -292,-930.17 6308,-930.17 ; -292,-726.83 6310,-726.83 ; -292,-523.5 -292,-1133.5 3713,-1133.5 6310,-1133.5 6310,-523.5 -291.5,-523.5 -291.5,-1133.5 1284,-1133.5 ; 2173,-1133.5 2173,-523.5 ; 3440,-726.83 3440,-523.5 ; 4280,-726.83 4280,-523.5 ; 4902,-1140 4902,-937.17
  text "ALL ARTWORK VIEWED FROM TOP SIDE" at -228.5,-655.67 h60
  text "BOARD #:" at 2248,-655.67 h60
  text ".PRJ_Number" at 2793.5,-655.67 h60
  text "REV:" at 3638,-655.67 h60
  text ".PCB_Rev" at 3929.5,-655.67 h60
  text "SVN REV:" at 4476,-655.67 h60
  text ".VersionControl_RevNumber" at 4982,-655.67 h60
  text "LAYER NAME =" at -228.5,-858.49 h60
  text "PLOT NAME =" at -228.5,-1064.34 h60
  text ".plot_File_Name" at 577,-1064.34 h60
  text "GENERATED    :" at 2250,-1064.34 h60
  text ".Print_Date" at 3119.5,-1064.34 h60
  text ".Print_Time" at 3848.5,-1064.34 h60
  text "TEXAS INSTRUMENTS" at 5113,-1064.34 h60
M12 Stackup:
  drawing of 165 lines, arcs and shapes, not listed
  text "Layer" at 9791.53,7669.89 h60
  text "Name" at 10201.44,7669.89 h60
  text "Material" at 11061.21,7669.89 h60
  text "Thickness" at 11920.98,7669.89 h60
  text "Constant" at 12570.81,7669.89 h60
  text "Board Layer Stack" at 13140.67,7669.89 h60
  text "1" at 9791.53,7549.89 h60
  text "Top Overlay" at 10201.44,7549.89 h60
  text "2" at 9791.53,7429.89 h60
  text "Top Solder" at 10201.44,7429.89 h60
  text "Solder Resist" at 11061.21,7429.89 h60
  text "0.40mil" at 11920.98,7429.89 h60
  text "3.5" at 12570.81,7429.89 h60
  text "3" at 9791.53,7309.89 h60
  text "Top Layer" at 10201.44,7309.89 h60
  text "Copper" at 11061.21,7309.89 h60
  text "1.40mil" at 11920.98,7309.89 h60
  text "4" at 9791.53,7189.89 h60
  text "Dielectric1" at 10201.44,7189.89 h60
  text "FR-4" at 11061.21,7189.89 h60
  text "37.20mil" at 11920.98,7189.89 h60
  text "4.8" at 12570.81,7189.89 h60
  text "5" at 9791.53,7069.89 h60
  text "Bottom Layer" at 10201.44,7069.89 h60
  text "Copper" at 11061.21,7069.89 h60
  text "1.40mil" at 11920.98,7069.89 h60
  text "6" at 9791.53,6949.89 h60
  text "Bottom Solder" at 10201.44,6949.89 h60
  text "Solder Resist" at 11061.21,6949.89 h60
  text "0.40mil" at 11920.98,6949.89 h60
  text "3.5" at 12570.81,6949.89 h60
  text ".Layer_Name" at 577,-858.49 h60
M13 Component Bodies Top:
  text ".Layer_Name" at 577,-858.49 h60
M14 Component Bodies Bottom:
  text ".Layer_Name" at 577,-858.49 h60
M15 Courtyards Top:
  text ".Layer_Name" at 577,-858.49 h60
M16 Courtyards Bottom:
  text ".Layer_Name" at 577,-858.49 h60
Drill Drawing:
  circle w10: c2850.43,1648.95 r27.63
  lines w10: 2822.8,1759.45 2836.62,1759.45 2850.43,1745.64 2864.24,1759.45 2878.06,1759.45 2864.24,1773.27 2878.06,1787.08 2864.24,1787.08 2850.43,1800.89 2836.62,1787.08 2822.8,1787.08 2836.62,1773.27 2822.8,1759.45 ; 2822.8,1869.96 2850.43,1883.77 2878.06,1869.96 2864.24,1897.59 2878.06,1925.21 2850.43,1911.4 2822.8,1925.21 2836.62,1897.59 2822.8,1869.96 ; 2822.8,1994.28 2878.06,1994.28 2878.06,2049.53 2822.8,2049.53 2822.8,1994.28
  lines w12: 2772.71,1584.02 6004.2,1584.02 ; 2772.71,2081.3 6004.2,2081.3 ; 3110.57,1459.7 3110.57,2205.62 ; 3442.58,1459.7 3442.58,2205.62 ; 4079.14,1459.7 4079.14,2205.62 ; 4338.28,1459.7 4338.28,2205.62 ; 4713.44,1459.7 4713.44,2205.62 ; 5437.77,1459.7 5437.77,2205.62 ; 2772.71,1459.7 6004.2,1459.7 6004.2,2205.62 2772.71,2205.62 2772.71,1459.7
  text "Symbol" at 2847.3,2118.6 h72
  text "Quantity" at 3147.87,2118.6 h72
  text "Finished Hole Size" at 3479.87,2118.6 h72
  text "Plated" at 4116.43,2118.6 h72
  text "Hole Type" at 4375.57,2118.6 h72
  text "Drill Layer Pair" at 4750.73,2118.6 h72
  text "Hole Tolerance" at 5475.06,2118.6 h72
  text "6" at 3147.87,1994.28 h60
  text "6.00mil (0.152mm)" at 3479.87,1994.28 h60
  text "PTH" at 4116.43,1994.28 h60
  text "Round" at 4375.57,1994.28 h60
  text "Top Layer - Bottom Layer" at 4750.73,1994.28 h60
  text "44" at 3147.87,1869.96 h60
  text "8.00mil (0.203mm)" at 3479.87,1869.96 h60
  text "PTH" at 4116.43,1869.96 h60
  text "Round" at 4375.57,1869.96 h60
  text "Top Layer - Bottom Layer" at 4750.73,1869.96 h60
  text "19" at 3147.87,1745.64 h60
  text "40.00mil (1.016mm)" at 3479.87,1745.64 h60
  text "PTH" at 4116.43,1745.64 h60
  text "Round" at 4375.57,1745.64 h60
  text "Top Layer - Bottom Layer" at 4750.73,1745.64 h60
  text "4" at 3147.87,1621.32 h60
  text "50.00mil (1.270mm)" at 3479.87,1621.32 h60
  text "PTH" at 4116.43,1621.32 h60
  text "Round" at 4375.57,1621.32 h60
  text "Top Layer - Bottom Layer" at 4750.73,1621.32 h60
  text "73 Total" at 3147.87,1497 h60
  text ".Layer_Name" at 577,-858.49 h60

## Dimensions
0,0 to 2600,0 on M2 Board Dimensions
0,0 to 0,2200 on M2 Board Dimensions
